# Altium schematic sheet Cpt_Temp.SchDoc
size A4
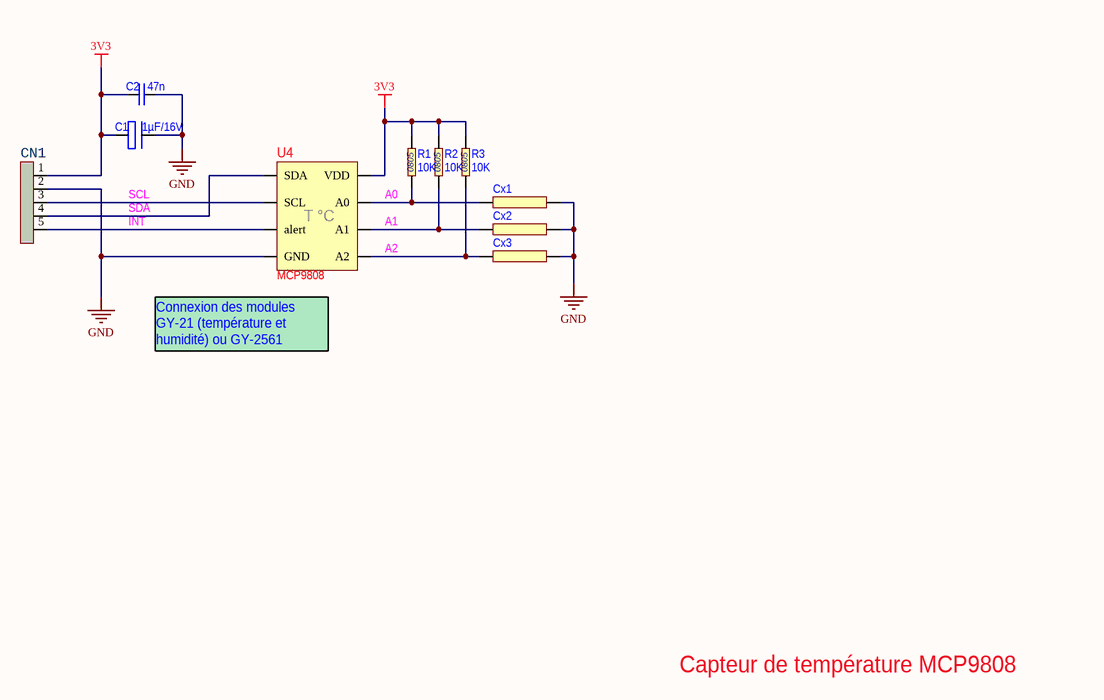
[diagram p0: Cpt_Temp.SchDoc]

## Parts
C1  1µF/16V  [3216-18]
C2  47n  [0805]
CN1  inch_ligne 1x5  [INCH_1x5_droit]  (value not drawn)
Cx1  Pont  [0402]  (value not drawn)
Cx2  Pont  [0402]  (value not drawn)
Cx3  Pont  [0402]  (value not drawn)
R1  10K  [0805]
R2  10K  [0805]
R3  10K  [0805]
U4  MCP9808  [MSOP-08]

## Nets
3V3: C1.1(V+) C2.1(CT1) CN1.1 R1.2(CT2) R2.2(CT2) R3.2(CT2) U4.8(VDD)
GND: C1.2(V-) C2.2(CT2) CN1.2 Cx1.2(P2) Cx2.2(P2) Cx3.2(P2) U4.4(GND)
A0: Cx1.1(P1) R1.1(CT1) U4.7(A0)
A1: Cx2.1(P1) R2.1(CT1) U4.6(A1)
A2: Cx3.1(P1) R3.1(CT1) U4.5(A2)
INT: CN1.5 U4.3(alert)
SCL: CN1.3 U4.2(SCL)
SDA: CN1.4 U4.1(SDA)

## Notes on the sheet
- (near U4) Connexion des modules GY-21 (température et humidité) ou GY-2561 (Luxmètre)
- Capteur de température MCP9808

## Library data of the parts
C1 = tantale 1µF/16V: 145-7406 case 3216-18
C2 = Cap_CMS_0805: CMS 0805
CN1 = Inch_1x5_droit
Cx1-Cx3 = Pont: Pont pour configuration I2C
R1-R3 = Res CMS 0805: CMS 0805
U4 = MCP9808: Digital temperature Sensor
